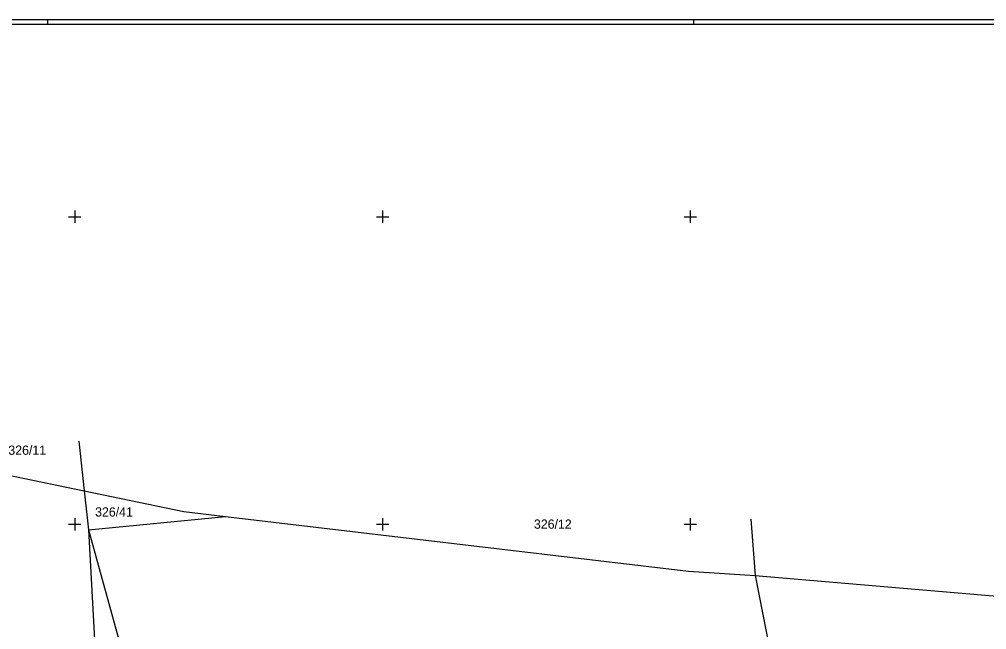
# Model space of a CAD drawing. Extents: x -704057 to -703795, y -1008732 to -1008584.
# Drawn here: x -703954.5 to -703875.9, y -1008633.6 to -1008584 of the extents above; entities that cross this region are included whole.
import ezdxf

# ---------------------------------------------------------------- set-up
doc = ezdxf.new("R2010")
doc.units = 0
for name, color, linetype in [('Z_hekt_sit', 7, 'Continuous'), ('Z_katastr_cisla_pozemkove', 7, 'Continuous'), ('Z_katastr_hranice', 7, 'Continuous'), ('Z_plotbox', 7, 'Continuous'), ('Z_ramecek_tisk', 7, 'Continuous')]:
    doc.layers.add(name, color=color, linetype=linetype)

msp = doc.modelspace()

# ---------------------------------------------------------------- linework, layer by layer
at = {"layer": 'Z_hekt_sit'}
for p, q in [((-703950.5, -1008600), (-703949.5, -1008600)), ((-703950, -1008599.5), (-703950, -1008600.5)), ((-703925.5, -1008600), (-703924.5, -1008600)), ((-703925, -1008599.5), (-703925, -1008600.5)), ((-703900.5, -1008600), (-703899.5, -1008600)), ((-703900, -1008599.5), (-703900, -1008600.5)), ((-703950.5, -1008625), (-703949.5, -1008625)), ((-703950, -1008624.5), (-703950, -1008625.5)), ((-703925.5, -1008625), (-703924.5, -1008625)), ((-703925, -1008624.5), (-703925, -1008625.5)), ((-703900.5, -1008625), (-703899.5, -1008625)), ((-703900, -1008624.5), (-703900, -1008625.5))]:
    msp.add_line(p, q, dxfattribs=at)
at = {"layer": 'Z_katastr_hranice'}
for p, q in [((-703968.91, -1008618.17), (-703949.24, -1008622.28)), ((-703949.68, -1008618.25), (-703949.24, -1008622.28)), ((-703949.24, -1008622.28), (-703948.89, -1008625.45)), ((-703949.24, -1008622.28), (-703941.15, -1008623.97)), ((-703948.89, -1008625.45), (-703937.76, -1008624.37)), ((-703941.15, -1008623.97), (-703937.76, -1008624.37)), ((-703937.76, -1008624.37), (-703900.14, -1008628.81)), ((-703895.08, -1008624.57), (-703894.73, -1008629.15)), ((-703948.89, -1008625.45), (-703948.06, -1008640.63)), ((-703948.89, -1008625.45), (-703944.54, -1008641.19)), ((-703900.14, -1008628.81), (-703894.73, -1008629.15)), ((-703894.73, -1008629.15), (-703891.93, -1008643.46)), ((-703894.73, -1008629.15), (-703843.9, -1008633.54))]:
    msp.add_line(p, q, dxfattribs=at)
at = {"layer": 'Z_plotbox'}
for p, q in [((-704057.23, -1008583.96), (-703794.73, -1008583.96)), ((-703952.23, -1008583.96), (-703952.23, -1008584.34)), ((-703899.73, -1008583.96), (-703899.73, -1008584.34))]:
    msp.add_line(p, q, dxfattribs=at)
at = {"layer": 'Z_ramecek_tisk'}
msp.add_line((-704056.86, -1008584.34), (-703795.11, -1008584.34), dxfattribs=at)

# ---------------------------------------------------------------- texts
at = {"layer": 'Z_katastr_cisla_pozemkove'}
for s, p in [('326/11', (-703955.4, -1008619.35)), ('326/41', (-703948.35, -1008624.37)), ('326/12', (-703912.7, -1008625.36))]:
    msp.add_text(s, height=0.75, dxfattribs=at).set_placement(p)

doc.saveas('drawing.dxf')
